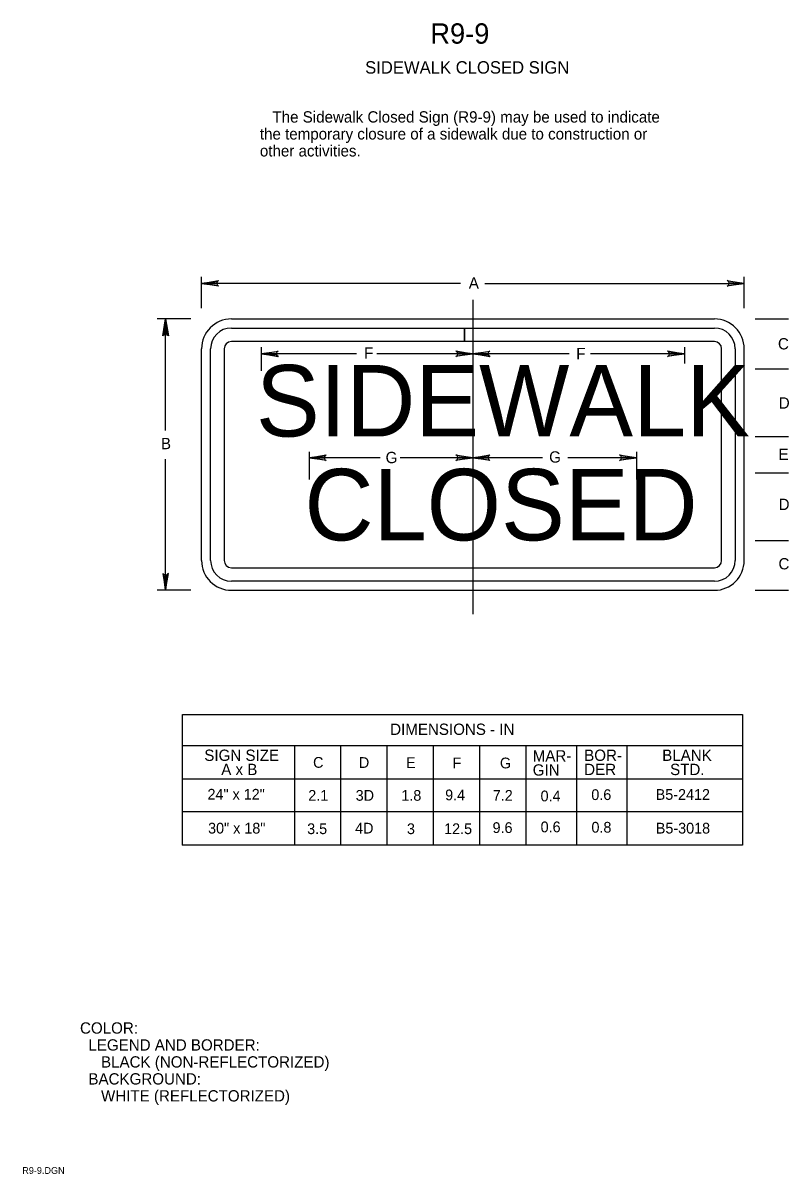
# Model space of a CAD drawing. Extents: x 0.013 to 0.182, y 0.005 to 0.259.
import ezdxf

# ---------------------------------------------------------------- set-up
doc = ezdxf.new("R2010")
doc.units = 0
for name, color, linetype in [('1', 7, 'Continuous'), ('2', 7, 'Continuous'), ('3', 7, 'Continuous')]:
    doc.layers.add(name, color=color, linetype=linetype)

# ---------------------------------------------------------------- blocks, each defined once
blk = doc.blocks.new('RARROW')
at = {"layer": '3'}
for p, q in [((-2.156, 0.285), (-2.2665, 0.384625)), ((-2.2665, 0.384625), (0, 0)), ((0, 0), (-2.2665, -0.379125)), ((-2.156, 0.285), (-2.075625, 0.12075)), ((0, 0), (-2.156, 0.285)), ((-2.14975, -0.2705), (0, 0)), ((-2.075625, 0.12075), (0, 0)), ((0, 0), (-2.074, -0.108)), ((-2.2665, -0.379125), (-2.14975, -0.2705)), ((-2.074, -0.108), (-2.14975, -0.2705))]:
    blk.add_line(p, q, dxfattribs=at)

msp = doc.modelspace()

# ---------------------------------------------------------------- linework, layer by layer
at = {"layer": '1'}
for p, q in [((0.112, 0.198), (0.112, 0.12848)), ((0.04961, 0.19375), (0.04221, 0.19375)), ((0.17439, 0.19375), (0.18179, 0.19375)), ((0.0586, 0.19175), (0.11012, 0.19175)), ((0.11012, 0.19175), (0.11012, 0.18875)), ((0.11012, 0.18875), (0.11012, 0.19175)), ((0.11012, 0.19175), (0.1654, 0.19175)), ((0.11012, 0.18875), (0.0586, 0.18875)), ((0.1654, 0.18875), (0.11012, 0.18875)), ((0.054, 0.14035), (0.054, 0.18715)), ((0.057, 0.18715), (0.057, 0.14035)), ((0.0652, 0.18748), (0.0652, 0.18229)), ((0.1588, 0.18748), (0.1588, 0.18392)), ((0.167, 0.14035), (0.167, 0.18715)), ((0.17, 0.18715), (0.17, 0.14035)), ((0.17439, 0.18275), (0.18179, 0.18275)), ((0.17439, 0.16775), (0.18179, 0.16775)), ((0.0758, 0.16435), (0.0758, 0.15828)), ((0.1482, 0.16435), (0.1482, 0.15828)), ((0.17439, 0.15975), (0.18179, 0.15975)), ((0.17439, 0.14475), (0.18179, 0.14475)), ((0.0586, 0.13875), (0.1654, 0.13875)), ((0.1654, 0.13575), (0.0586, 0.13575)), ((0.04961, 0.13375), (0.04221, 0.13375)), ((0.17439, 0.13375), (0.18179, 0.13375))]:
    msp.add_line(p, q, dxfattribs=at)
for centre, radius, start, end in [((0.0586, 0.18715), 0.0066, 90, 180), ((0.1654, 0.18715), 0.0066, 0, 90), ((0.0586, 0.18715), 0.0046, 90, 180), ((0.1654, 0.18715), 0.0046, 0, 90), ((0.0586, 0.18715), 0.0016, 90, 180), ((0.1654, 0.18715), 0.0016, 0, 90), ((0.0586, 0.14035), 0.0066, 180, 270), ((0.0586, 0.14035), 0.0046, 180, 270), ((0.0586, 0.14035), 0.0016, 180, 270), ((0.1654, 0.14035), 0.0066, 270, 0), ((0.1654, 0.14035), 0.0016, 270, 0), ((0.1654, 0.14035), 0.0046, 270, 0)]:
    msp.add_arc(centre, radius, start, end, dxfattribs=at)
at = {"layer": '3'}
for p, q in [((0.052, 0.19613), (0.052, 0.20304)), ((0.10928, 0.20161), (0.052, 0.20161)), ((0.11463, 0.20161), (0.172, 0.20161)), ((0.172, 0.19613), (0.172, 0.20304)), ((0.04405, 0.1691), (0.04405, 0.19375)), ((0.0586, 0.19375), (0.1654, 0.19375)), ((0.052, 0.14035), (0.052, 0.18715)), ((0.0863, 0.18604), (0.0652, 0.18604)), ((0.112, 0.18604), (0.09075, 0.18604)), ((0.13329, 0.18604), (0.112, 0.18604)), ((0.1588, 0.18604), (0.13803, 0.18604)), ((0.172, 0.14035), (0.172, 0.18715)), ((0.09149, 0.16307), (0.0758, 0.16307)), ((0.112, 0.16307), (0.09594, 0.16307)), ((0.12736, 0.16307), (0.112, 0.16307)), ((0.1482, 0.16307), (0.13299, 0.16307)), ((0.04405, 0.13375), (0.04405, 0.16272)), ((0.0586, 0.13375), (0.1654, 0.13375)), ((0.04773, 0.10627), (0.04773, 0.07739)), ((0.04778, 0.10626), (0.17165, 0.10626)), ((0.17165, 0.10626), (0.17165, 0.07739)), ((0.17165, 0.09939), (0.04773, 0.09939)), ((0.07253, 0.09939), (0.07253, 0.07739)), ((0.08273, 0.09939), (0.08273, 0.07739)), ((0.09298, 0.09939), (0.09298, 0.07739)), ((0.10323, 0.09939), (0.10323, 0.07739)), ((0.11348, 0.09939), (0.11348, 0.07739)), ((0.12373, 0.09939), (0.12373, 0.07739)), ((0.1349, 0.09939), (0.1349, 0.07739)), ((0.14603, 0.09939), (0.14603, 0.07739)), ((0.17165, 0.09202), (0.04773, 0.09202)), ((0.17165, 0.08477), (0.04773, 0.08477)), ((0.17165, 0.07739), (0.04773, 0.07739))]:
    msp.add_line(p, q, dxfattribs=at)

# ---------------------------------------------------------------- block references
at = {"layer": '3', "xscale": 0.001654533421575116}
for p, yscale, rotation in [((0.052, 0.20161), 0.0016366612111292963, 180), ((0.04405, 0.19375), 0.0016366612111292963, 89.99999999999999), ((0.0652, 0.18604), 0.0016366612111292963, 180), ((0.112, 0.18604), 0.0016366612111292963, 180), ((0.0758, 0.16307), 0.0016366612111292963, 180), ((0.112, 0.16307), 0.0016366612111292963, 180), ((0.04405, 0.13375), -0.0016366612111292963, -89.99999999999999)]:
    msp.add_blockref('RARROW', p, dxfattribs=dict(at, yscale=yscale, rotation=rotation))
at = {"layer": '3', "xscale": 0.001654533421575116, "yscale": 0.0016366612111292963}
for p in [(0.172, 0.20161), (0.112, 0.18604), (0.1588, 0.18604), (0.112, 0.16307), (0.1482, 0.16307)]:
    msp.add_blockref('RARROW', p, dxfattribs=at)

# ---------------------------------------------------------------- texts
at = {"layer": '1'}
for s, height, p in [('R9-9', 0.0045, (0.1026, 0.25462)), ('SIDEWALK CLOSED SIGN', 0.0027503, (0.08817, 0.248)), ('COLOR:', 0.0025, (0.02513, 0.03571)), ('  LEGEND AND BORDER:', 0.0024998, (0.02513, 0.03196)), ('     BLACK (NON-REFLECTORIZED) ', 0.0024998, (0.02513, 0.02821)), ('  BACKGROUND:', 0.0024998, (0.02513, 0.02446)), ('     WHITE (REFLECTORIZED)          ', 0.0024998, (0.02513, 0.02071)), ('R9-9.DGN', 0.0015, (0.01236, 0.0047))]:
    msp.add_text(s, height=height, dxfattribs=at).set_placement(p)
for s, p in [('SIDEWALK', (0.06403, 0.16776)), ('CLOSED', (0.07476, 0.14479))]:
    msp.add_text(s, height=0.015809, rotation=360, dxfattribs=at).set_placement(p)
at = {"layer": '2'}
for s, p in [('   The Sidewalk Closed Sign (R9-9) may be used to indicate', (0.0649, 0.23718)), ('the temporary closure of a sidewalk due to construction or', (0.0649, 0.23343)), ('other activities.', (0.0649, 0.22968))]:
    msp.add_text(s, height=0.0024998, dxfattribs=at).set_placement(p)
at = {"layer": '3'}
for s, height, p in [('A', 0.0025, (0.1111, 0.20047)), ('C', 0.0025, (0.17946, 0.18701)), ('F', 0.0025, (0.08794, 0.18497)), ('D', 0.0025, (0.17964, 0.17392)), ('B', 0.0025, (0.04302, 0.16495)), ('G', 0.0025, (0.0927, 0.16186)), ('E', 0.0025, (0.17958, 0.16258)), ('DIMENSIONS - IN', 0.0024998, (0.09371, 0.10177)), ('SIGN SIZE', 0.0025, (0.05261, 0.09602)), ('C', 0.00238, (0.07666, 0.0945)), ('D', 0.00238, (0.08679, 0.09447)), ('E', 0.00238, (0.09721, 0.09444)), ('F', 0.00238, (0.10749, 0.09439)), ('G', 0.00238, (0.11798, 0.09437)), ('MAR-', 0.0025, (0.12523, 0.09589)), ('BOR-', 0.0025, (0.13661, 0.09602)), ('BLANK', 0.0025, (0.15386, 0.09602)), ('A x B', 0.0025, (0.05636, 0.09289)), ('GIN', 0.0025, (0.12523, 0.09277)), ('DER', 0.0025, (0.13661, 0.09289)), ('STD.', 0.0025, (0.15561, 0.09289)), ('24" x 12"', 0.002375, (0.05332, 0.08746)), ('2.1', 0.002375, (0.0756, 0.08721)), ('3D', 0.002375, (0.08608, 0.08721)), ('1.8', 0.002375, (0.09618, 0.08721)), ('9.4', 0.002375, (0.10587, 0.08731)), ('7.2', 0.002375, (0.1164, 0.08721)), ('0.4', 0.002375, (0.12697, 0.08708)), ('0.6', 0.002375, (0.13819, 0.08737)), ('B5-2412', 0.002375, (0.15242, 0.08741)), ('30" x 18"', 0.002375, (0.05345, 0.07996)), ('3.5', 0.002375, (0.07536, 0.07983)), ('4D', 0.002375, (0.08596, 0.07996)), ('3', 0.00238, (0.09742, 0.07983)), ('12.5', 0.002375, (0.10564, 0.07983)), ('9.6', 0.002375, (0.11635, 0.08008)), ('0.6', 0.002375, (0.12698, 0.08024)), ('0.8', 0.002375, (0.13822, 0.08016)), ('B5-3018', 0.002375, (0.15245, 0.07996))]:
    msp.add_text(s, height=height, dxfattribs=at).set_placement(p)
for s, p in [('F', (0.13485, 0.18485)), ('G', (0.12887, 0.16198)), ('D', (0.17961, 0.1515)), ('C', (0.17958, 0.13837))]:
    msp.add_text(s, height=0.0025, rotation=360, dxfattribs=at).set_placement(p)

doc.saveas('drawing.dxf')
